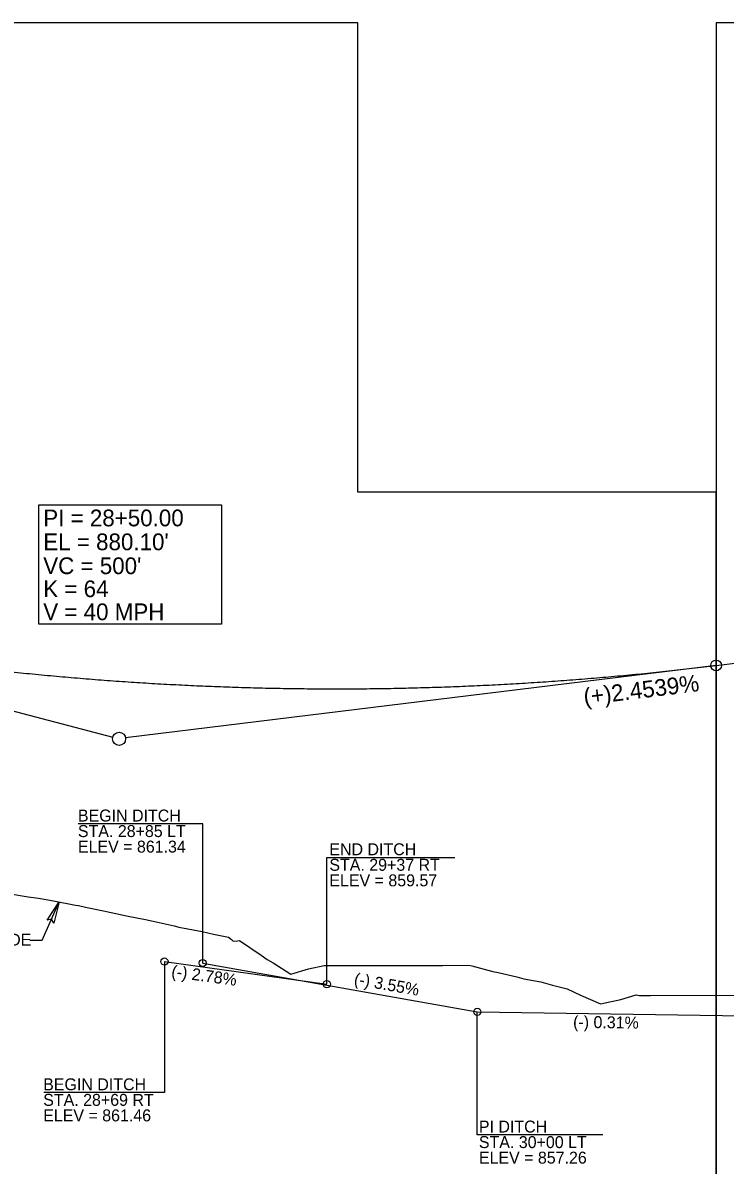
# Model space of a CAD drawing. Extents: x 1968019 to 1983409, y 545058 to 567558.
# Drawn here: x 1970652.7 to 1970946.7, y 566530.6 to 567008.4 of the extents above; entities that cross this region are included whole.
import ezdxf

# ---------------------------------------------------------------- set-up
doc = ezdxf.new("R2010")
doc.units = 0
for name, color, linetype in [('Exist Vertical Profile Ground Line', 7, 'Continuous'), ('Old_Level_20', 7, 'Continuous'), ('Prop Grid Mask', 7, 'Continuous'), ('Prop Terminator CELL', 7, 'Continuous'), ('Prop Vertical Profile Curve Label', 7, 'Continuous'), ('Prop Vertical Profile Ditch Grade Left', 7, 'Continuous'), ('Prop Vertical Profile Ditch Grade Left Label', 7, 'Continuous'), ('Prop Vertical Profile Ditch Grade Right', 7, 'Continuous'), ('Prop Vertical Profile Ditch Grade Right Label', 7, 'Continuous'), ('Prop Vertical Profile Grade', 7, 'Continuous'), ('Prop Vertical Profile Grade Label', 7, 'Continuous'), ('Prop VPI Label', 7, 'Continuous'), ('Scratch_Level_8', 7, 'Continuous')]:
    doc.layers.add(name, color=color, linetype=linetype)

msp = doc.modelspace()

# ---------------------------------------------------------------- linework, layer by layer
at = {"layer": 'Exist Vertical Profile Ground Line'}
for points in [[(1970646.66, 566644.27), (1970654.94, 566642.83), (1970659.2, 566642.23), (1970665.47, 566641.18), (1970674.67, 566639.37), (1970675.96, 566639.15), (1970678.85, 566638.5), (1970686.4, 566636.95), (1970689.59, 566636.28), (1970696.81, 566634.79), (1970704.02, 566633.28), (1970707.17, 566632.64), (1970716, 566630.63), (1970717.51, 566630.28), (1970718.02, 566630.19), (1970727.8, 566628.26), (1970732.52, 566627.24), (1970738.82, 566625.93), (1970740.02, 566624.92), (1970740.66, 566624.25), (1970742.55, 566624.41), (1970743.43, 566624.57), (1970752.49, 566618.43), (1970754.96, 566616.65), (1970757.53, 566615.14), (1970764.88, 566610.5)], [(1970764.88, 566610.5), (1970772.33, 566612.63), (1970778.86, 566614.15), (1970828.34, 566614.13), (1970839.41, 566614.24), (1970840.66, 566613.96), (1970849.45, 566611.62), (1970851.66, 566611.21), (1970859.48, 566609.31), (1970862.47, 566608.51), (1970869.5, 566607.3), (1970874.45, 566605.81), (1970880.64, 566604.28), (1970886.11, 566601.66), (1970894.54, 566598.08), (1970903.1, 566599.92), (1970909.53, 566601.87), (1970910.84, 566601.55), (1970915.49, 566601.57), (1970957.3, 566601.67)]]:
    msp.add_lwpolyline(points, dxfattribs=at)
at = {"layer": 'Old_Level_20'}
for p, q in [((1970660.76, 566624.66), (1970667.89, 566640.66)), ((1970655.59, 566624.66), (1970660.76, 566624.66))]:
    msp.add_line(p, q, dxfattribs=at)
at = {"layer": 'Prop Grid Mask'}
msp.add_lwpolyline([(1970659.37, 566806.76), (1970735.88, 566806.76), (1970735.88, 566756.82), (1970659.37, 566756.82)], close=True, dxfattribs=at)
at = {"layer": 'Prop Terminator CELL'}
msp.add_lwpolyline([(1970662.81, 566633.07), (1970667.89, 566640.66), (1970665.67, 566631.74), (1970664.68, 566633.44)], close=True, dxfattribs=at)
at = {"layer": 'Prop Vertical Profile Curve Label'}
msp.add_circle((1970942.96, 566739.6), 2.25, dxfattribs=at)
at = {"layer": 'Prop Vertical Profile Ditch Grade Left'}
msp.add_lwpolyline([(1970727.96, 566615.13), (1970842.96, 566594.73), (1970982.96, 566592.58)], dxfattribs=at)
at = {"layer": 'Prop Vertical Profile Ditch Grade Left Label'}
for p, q in [((1970727.96, 566673.4), (1970675.81, 566673.4)), ((1970727.96, 566615.13), (1970727.96, 566673.4)), ((1970842.96, 566543.28), (1970842.96, 566594.73)), ((1970895.47, 566543.28), (1970842.96, 566543.28))]:
    msp.add_line(p, q, dxfattribs=at)
for centre in [(1970727.96, 566615.13), (1970842.96, 566594.73)]:
    msp.add_circle(centre, 1.5, dxfattribs=at)
at = {"layer": 'Prop Vertical Profile Ditch Grade Right'}
msp.add_line((1970711.96, 566615.73), (1970779.96, 566606.28), dxfattribs=at)
at = {"layer": 'Prop Vertical Profile Ditch Grade Right Label'}
for p, q in [((1970779.96, 566606.28), (1970779.96, 566659.26)), ((1970779.96, 566659.26), (1970833.54, 566659.26)), ((1970711.96, 566615.73), (1970711.96, 566560.95)), ((1970711.96, 566560.95), (1970661.41, 566560.95))]:
    msp.add_line(p, q, dxfattribs=at)
for centre in [(1970711.96, 566615.73), (1970779.96, 566606.28)]:
    msp.add_circle(centre, 1.5, dxfattribs=at)
at = {"layer": 'Prop Vertical Profile Grade'}
msp.add_line((1970942.96, 566739.6), (1971612.96, 566821.8), dxfattribs=at)
msp.add_spline([(1970442.96, 566774.61), (1970452.96, 566772.02), (1970462.96, 566769.51), (1970472.96, 566767.07), (1970482.96, 566764.71), (1970492.96, 566762.43), (1970502.96, 566760.23), (1970512.96, 566758.1), (1970522.96, 566756.05), (1970532.96, 566754.08), (1970542.96, 566752.19), (1970552.96, 566750.37), (1970562.96, 566748.63), (1970572.96, 566746.96), (1970582.96, 566745.38), (1970592.96, 566743.87), (1970602.96, 566742.44), (1970612.96, 566741.08), (1970622.96, 566739.8), (1970632.96, 566738.6), (1970642.96, 566737.48), (1970652.96, 566736.43), (1970662.96, 566735.46), (1970672.96, 566734.57), (1970682.96, 566733.75), (1970692.96, 566733.01), (1970702.96, 566732.35), (1970712.96, 566731.77), (1970722.96, 566731.26), (1970732.96, 566730.83), (1970742.96, 566730.47), (1970752.96, 566730.2), (1970762.96, 566730), (1970772.96, 566729.88), (1970782.96, 566729.83), (1970792.96, 566729.86), (1970802.96, 566729.97), (1970812.96, 566730.16), (1970822.96, 566730.42), (1970832.96, 566730.76), (1970842.96, 566731.18), (1970852.96, 566731.68), (1970862.96, 566732.25), (1970872.96, 566732.9), (1970882.96, 566733.62), (1970892.96, 566734.43), (1970902.96, 566735.31), (1970912.96, 566736.26), (1970922.96, 566737.3), (1970932.96, 566738.41), (1970942.96, 566739.6)], degree=3, dxfattribs=at)
at = {"layer": 'Prop VPI Label'}
for p, q in [((1970442.96, 566774.61), (1970690.3, 566709.62)), ((1970942.96, 566739.6), (1970695.69, 566709.26))]:
    msp.add_line(p, q, dxfattribs=at)
msp.add_circle((1970692.96, 566708.92), 2.75, dxfattribs=at)
at = {"layer": 'Scratch_Level_8'}
for points in [[(1969542.96, 566508.43), (1970942.96, 566508.43), (1970942.96, 566812.08), (1970792.94, 566812.08), (1970792.94, 567008.42), (1969542.96, 567008.43)], [(1970942.96, 566508.43), (1972342.96, 566508.43), (1972342.96, 567008.43), (1970942.96, 567008.43)]]:
    msp.add_lwpolyline(points, close=True, dxfattribs=at)

# ---------------------------------------------------------------- texts
at = {"layer": 'Old_Level_20'}
msp.add_text('EXISTING GRADE', height=5, rotation=360, dxfattribs=at).set_placement((1970599.37, 566622.39))
at = {"layer": 'Prop Vertical Profile Curve Label'}
for s, p in [("VC = 500'", (1970661.21, 566777.81)), ('K = 64', (1970661.21, 566768.18)), ('V = 40 MPH', (1970661.21, 566758.55))]:
    msp.add_text(s, height=7, dxfattribs=at).set_placement(p)
at = {"layer": 'Prop Vertical Profile Ditch Grade Left Label'}
for s, p in [('BEGIN DITCH', (1970675.72, 566674.32)), ('STA. 28+85 LT', (1970675.72, 566667.82)), ('ELEV = 861.34', (1970675.72, 566661.32)), ('PI DITCH', (1970843.62, 566544.21)), ('STA. 30+00 LT', (1970843.62, 566537.71)), ('ELEV = 857.26', (1970843.62, 566531.21))]:
    msp.add_text(s, height=5, dxfattribs=at).set_placement(p)
for s, rotation, p in [('(-) 3.55%', 349.9409, (1970791.07, 566606.16)), ('(-) 0.31%', 359.1202, (1970883.04, 566588.06))]:
    msp.add_text(s, height=5, rotation=rotation, dxfattribs=at).set_placement(p)
at = {"layer": 'Prop Vertical Profile Ditch Grade Right Label'}
for s, p in [('END DITCH', (1970781, 566660.21)), ('STA. 29+37 RT', (1970781, 566653.71)), ('ELEV = 859.57', (1970781, 566647.21)), ('BEGIN DITCH', (1970661.18, 566561.88)), ('STA. 28+69 RT', (1970661.18, 566555.38)), ('ELEV = 861.46', (1970661.18, 566548.88))]:
    msp.add_text(s, height=5, dxfattribs=at).set_placement(p)
msp.add_text('(-) 2.78%', height=5, rotation=352.0882, dxfattribs=at).set_placement((1970714.65, 566609.32))
at = {"layer": 'Prop Vertical Profile Grade Label'}
msp.add_text('(+)2.4539%', height=7, rotation=6.995, dxfattribs=at).set_placement((1970887.88, 566722.98))
at = {"layer": 'Prop VPI Label'}
for s, p in [('PI = 28+50.00', (1970661.21, 566797.81)), ("EL = 880.10'", (1970661.21, 566787.81))]:
    msp.add_text(s, height=7, dxfattribs=at).set_placement(p)

doc.saveas('drawing.dxf')
